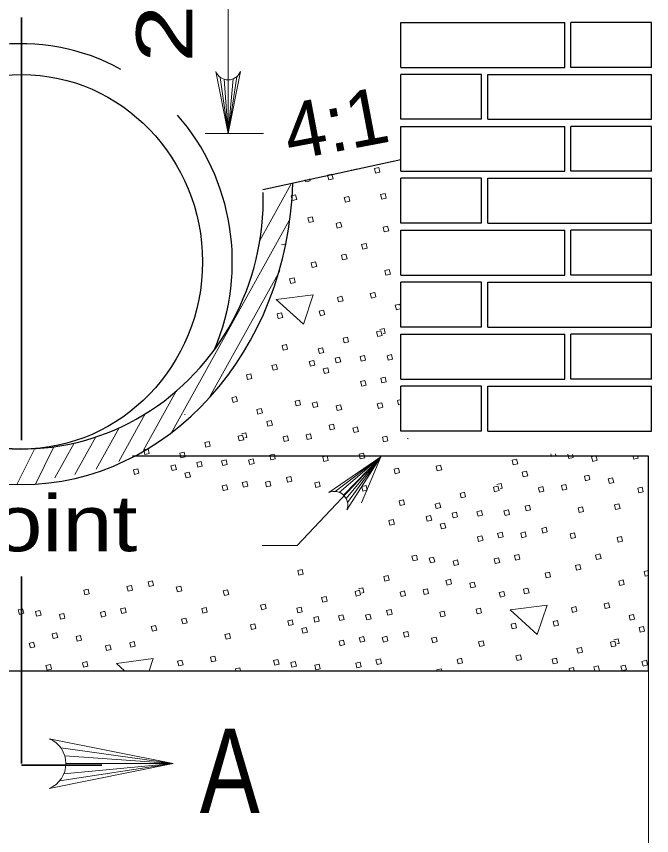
# Model space of a CAD drawing. Extents: x 750.7 to 784.7, y 860.1 to 882.1.
# Drawn here: x 763.779 to 765.592, y 862.482 to 864.82 of the extents above; entities that cross this region are included whole.
import ezdxf
from ezdxf.enums import TextEntityAlignment as Align

# ---------------------------------------------------------------- set-up
doc = ezdxf.new("R2010")
doc.units = 0
doc.header["$LTSCALE"] = 0.064
doc.layers.add('1', color=7, linetype='Continuous', lineweight=13)

msp = doc.modelspace()

# ---------------------------------------------------------------- linework, layer by layer
at = {"layer": '1'}
for p, q in [((764.38325, 864.48525), (764.38325, 864.95308)), ((764.36083, 864.64558), (764.38325, 864.48525)), ((764.40808, 864.6475), (764.38325, 864.48525)), ((764.37192, 864.64017), (764.38325, 864.48525)), ((764.39767, 864.64133), (764.38325, 864.48525)), ((764.38325, 864.6385), (764.38325, 864.48525)), ((764.48417, 864.48525), (764.31717, 864.48525)), ((764.47383, 864.18017), (764.56233, 864.3395)), ((764.21975, 863.62858), (764.55783, 864.23733)), ((764.53542, 864.16725), (764.54525, 864.16958)), ((764.33, 863.733), (764.53033, 864.09367)), ((764.8165, 863.92617), (764.82858, 863.929)), ((764.1415, 863.58175), (764.23475, 863.74975)), ((764.07142, 863.54967), (764.14667, 863.68525)), ((764.25867, 863.68333), (764.26083, 863.68383)), ((764.00667, 863.52733), (764.07233, 863.6455)), ((763.94592, 863.51208), (764.00533, 863.61917)), ((764.42142, 863.62842), (764.4335, 863.63133)), ((763.88825, 863.50242), (763.94342, 863.60167)), ((763.78042, 863.48383), (763.82992, 863.58292)), ((763.83325, 863.48492), (763.88517, 863.58883)), ((764.8195, 863.56292), (764.57992, 863.30967)), ((764.68883, 863.46375), (764.8195, 863.56292)), ((764.7005, 863.46092), (764.8195, 863.56292)), ((764.71283, 863.45292), (764.8195, 863.56292)), ((764.71983, 863.44392), (764.8195, 863.56292)), ((764.724, 863.43225), (764.8195, 863.56292)), ((764.8195, 863.56292), (764.76358, 863.43117)), ((765.15017, 863.48325), (765.16233, 863.48617)), ((764.4805, 863.30967), (764.57992, 863.30967)), ((765.58317, 863.23833), (765.58325, 863.23808)), ((764.75517, 863.18558), (764.76725, 863.18842)), ((765.58325, 863.15042), (765.58325, 862.085)), ((765.48392, 863.04033), (765.49608, 863.04325)), ((764.15792, 862.95208), (764.16958, 862.987)), ((765.36875, 862.9615), (765.371, 862.95208)), ((764.41642, 862.96033), (764.41842, 862.95208)), ((764.99175, 862.95733), (764.993, 862.95208)), ((763.90592, 862.73183), (764.2265, 862.687)), ((763.91675, 862.70967), (764.2265, 862.687)), ((763.90217, 862.63742), (764.2265, 862.687)), ((763.91442, 862.65817), (764.2265, 862.687)), ((763.92008, 862.687), (764.2265, 862.687))]:
    msp.add_line(p, q, dxfattribs=at)
at = {"layer": '1', "lineweight": 35}
for p, q in [((763.79367, 863.61058), (763.79367, 864.81675)), ((763.79367, 862.687), (763.79367, 863.22092)), ((764.02267, 862.68275), (763.79367, 862.68275))]:
    msp.add_line(p, q, dxfattribs=at)
at = {"layer": '1', "lineweight": 25}
for p, q in [((765.36175, 864.67417), (765.36175, 864.80217)), ((765.59183, 864.67417), (765.36175, 864.67417)), ((764.8765, 864.52583), (764.8765, 864.65392)), ((765.10658, 864.52583), (764.8765, 864.52583)), ((765.36175, 864.37758), (765.36175, 864.50567)), ((764.482, 864.32533), (764.8765, 864.41117)), ((765.59183, 864.37758), (765.36175, 864.37758)), ((764.8765, 864.22933), (764.8765, 864.35742)), ((765.10658, 864.22933), (764.8765, 864.22933)), ((765.36175, 864.08108), (765.36175, 864.20908)), ((764.8765, 863.93283), (764.8765, 864.06083)), ((765.59183, 864.08108), (765.36175, 864.08108)), ((765.10658, 863.93283), (764.8765, 863.93283)), ((765.36175, 863.7845), (765.36175, 863.91258)), ((765.59183, 863.7845), (765.36175, 863.7845)), ((764.8765, 863.63625), (764.8765, 863.76433)), ((765.10658, 863.63625), (764.8765, 863.63625)), ((765.58325, 863.56433), (764.10992, 863.56433)), ((765.58325, 862.95208), (765.58325, 863.56433)), ((760.59067, 862.95208), (765.58325, 862.95208))]:
    msp.add_line(p, q, dxfattribs=at)
for points in [[(764.8765, 864.67417), (764.8765, 864.80217), (765.34417, 864.80217)], [(764.8765, 864.67417), (765.34417, 864.67417), (765.34417, 864.80217)], [(765.59183, 864.67417), (765.59183, 864.80217), (765.36175, 864.80217)], [(765.10658, 864.52583), (765.10658, 864.65392), (764.8765, 864.65392)], [(765.12425, 864.52583), (765.12425, 864.65392), (765.59192, 864.65392)], [(765.12425, 864.52583), (765.59192, 864.52583), (765.59192, 864.65392)], [(764.8765, 864.37758), (764.8765, 864.50567), (765.34417, 864.50567)], [(764.8765, 864.37758), (765.34417, 864.37758), (765.34417, 864.50567)], [(765.59183, 864.37758), (765.59183, 864.50567), (765.36175, 864.50567)], [(765.10658, 864.22933), (765.10658, 864.35742), (764.8765, 864.35742)], [(765.12425, 864.22933), (765.12425, 864.35742), (765.59192, 864.35742)], [(765.12425, 864.22933), (765.59192, 864.22933), (765.59192, 864.35742)], [(764.8765, 864.08108), (764.8765, 864.20908), (765.34417, 864.20908)], [(764.8765, 864.08108), (765.34417, 864.08108), (765.34417, 864.20908)], [(765.59183, 864.08108), (765.59183, 864.20908), (765.36175, 864.20908)], [(765.10658, 863.93283), (765.10658, 864.06083), (764.8765, 864.06083)], [(765.12425, 863.93283), (765.12425, 864.06083), (765.59192, 864.06083)], [(765.12425, 863.93283), (765.59192, 863.93283), (765.59192, 864.06083)], [(764.8765, 863.7845), (764.8765, 863.91258), (765.34417, 863.91258)], [(764.8765, 863.7845), (765.34417, 863.7845), (765.34417, 863.91258)], [(765.59183, 863.7845), (765.59183, 863.91258), (765.36175, 863.91258)], [(765.10658, 863.63625), (765.10658, 863.76433), (764.8765, 863.76433)], [(765.12425, 863.63625), (765.12425, 863.76433), (765.59192, 863.76433)], [(765.12425, 863.63625), (765.59192, 863.63625), (765.59192, 863.76433)]]:
    msp.add_lwpolyline(points, dxfattribs=at)
at = {"layer": '1'}
for points in [[(764.41867, 864.66233), (764.38325, 864.48525), (764.34783, 864.66233)], [(764.74808, 864.384), (764.74825, 864.38325), (764.73575, 864.38025), (764.7355, 864.38133)], [(764.61583, 864.356), (764.61725, 864.35), (764.60467, 864.347), (764.60317, 864.35333)], [(764.82858, 863.929), (764.83175, 863.91575), (764.82542, 863.91425)], [(764.8765, 863.71208), (764.86967, 863.7105), (764.86642, 863.72375), (764.8765, 863.72608)], [(764.4335, 863.63133), (764.43675, 863.61808), (764.43042, 863.6165)], [(764.89658, 863.6145), (764.89567, 863.61433), (764.89533, 863.61583)], [(765.31758, 863.57092), (765.31875, 863.56608), (765.30617, 863.56308), (765.30425, 863.57125)], [(765.36592, 863.56967), (765.36808, 863.56075), (765.3555, 863.55775), (765.35258, 863.57)], [(764.67083, 863.46042), (764.8195, 863.56292), (764.72158, 863.41117)], [(765.55192, 863.56517), (765.5535, 863.55867), (765.54092, 863.55567), (765.53858, 863.5655)], [(765.16233, 863.48617), (765.1655, 863.47292), (765.15917, 863.47133)], [(765.58325, 863.42317), (765.58308, 863.42317), (765.58325, 863.423)], [(765.58325, 863.22433), (765.57383, 863.22208), (765.57058, 863.23533), (765.58317, 863.23833)], [(764.76725, 863.18842), (764.7705, 863.17517), (764.76408, 863.17367)], [(765.49608, 863.04325), (765.49925, 863.03), (765.49292, 863.02842)], [(764.16958, 862.987), (764.06417, 862.97292), (764.08733, 862.95208)], [(765.35775, 862.95208), (765.35617, 862.9585), (765.36875, 862.9615)], [(765.42983, 862.95208), (765.42717, 862.96317), (765.43975, 862.96617)], [(765.43975, 862.96617), (765.44292, 862.95292), (765.4395, 862.95208)], [(764.40517, 862.95208), (764.40392, 862.95733), (764.41642, 862.96033)], [(764.97967, 862.95208), (764.97917, 862.95433), (764.99175, 862.95733)], [(763.87242, 862.61617), (764.2265, 862.687), (763.87242, 862.75783)]]:
    msp.add_lwpolyline(points, dxfattribs=at)
for points in [[(764.81325, 864.38842), (764.81642, 864.37517), (764.80383, 864.37217), (764.80067, 864.38542)], [(764.67958, 864.36917), (764.68275, 864.35592), (764.67025, 864.353), (764.667, 864.36617)], [(764.57575, 864.3105), (764.579, 864.29725), (764.56642, 864.29425), (764.56317, 864.3075)], [(764.72725, 864.30592), (764.73042, 864.29267), (764.71792, 864.28967), (764.71467, 864.30292)], [(764.83108, 864.314), (764.83425, 864.30083), (764.82175, 864.29783), (764.8185, 864.31108)], [(764.62342, 864.24717), (764.62667, 864.23392), (764.61408, 864.231), (764.61092, 864.24425)], [(764.70425, 864.23183), (764.70742, 864.21858), (764.69483, 864.21558), (764.69167, 864.22883)], [(764.83825, 864.22108), (764.8415, 864.20783), (764.82892, 864.20483), (764.82567, 864.21808)], [(764.77683, 864.17108), (764.78, 864.15783), (764.76742, 864.15483), (764.76425, 864.16808)], [(764.71933, 864.14075), (764.7225, 864.12758), (764.70992, 864.12458), (764.70675, 864.13783)], [(764.63275, 864.11942), (764.63592, 864.10617), (764.62342, 864.10317), (764.62017, 864.11642)], [(764.84308, 864.097), (764.84625, 864.08375), (764.83375, 864.08075), (764.8305, 864.094)], [(764.57133, 864.07342), (764.5745, 864.06017), (764.56192, 864.05717), (764.55875, 864.07042)], [(764.626, 864.02525), (764.5205, 864.01125), (764.59808, 863.94158)], [(764.70792, 864.02075), (764.71108, 864.0075), (764.69858, 864.0045), (764.69533, 864.01775)], [(764.80158, 864.032), (764.80475, 864.01875), (764.79225, 864.01575), (764.789, 864.029)], [(764.87283, 863.99867), (764.876, 863.98542), (764.8635, 863.98242), (764.86025, 863.99567)], [(764.53567, 863.9735), (764.53892, 863.96025), (764.52633, 863.95733), (764.52317, 863.9705)], [(764.65583, 863.98158), (764.65908, 863.96833), (764.6465, 863.96533), (764.64333, 863.97858)], [(764.8195, 863.92217), (764.82267, 863.90892), (764.81008, 863.90592), (764.80692, 863.91917)], [(764.724, 863.90425), (764.72717, 863.891), (764.71458, 863.888), (764.71142, 863.90125)], [(764.54983, 863.88308), (764.553, 863.86983), (764.54042, 863.86683), (764.53725, 863.88008)], [(764.65283, 863.87383), (764.65608, 863.86058), (764.6435, 863.85758), (764.64033, 863.87083)], [(764.77225, 863.85192), (764.77542, 863.83867), (764.76292, 863.83567), (764.75967, 863.84892)], [(764.84942, 863.85425), (764.85258, 863.841), (764.84, 863.838), (764.83683, 863.85125)], [(764.52058, 863.82642), (764.52383, 863.81317), (764.51125, 863.81017), (764.50808, 863.82342)], [(764.62742, 863.83775), (764.63058, 863.8245), (764.618, 863.8215), (764.61483, 863.83475)], [(764.70125, 863.84725), (764.7045, 863.834), (764.69192, 863.831), (764.68867, 863.84425)], [(764.66742, 863.81642), (764.67058, 863.80317), (764.65808, 863.80017), (764.65483, 863.81342)], [(764.448, 863.79925), (764.45125, 863.786), (764.43867, 863.783), (764.43542, 863.79625)], [(764.77383, 863.78033), (764.777, 863.76708), (764.76442, 863.76408), (764.76125, 863.77733)], [(764.83133, 863.79), (764.8345, 863.77675), (764.82192, 863.77375), (764.81875, 863.787)], [(764.4065, 863.73433), (764.40975, 863.72108), (764.39717, 863.71808), (764.394, 863.73133)], [(764.58675, 863.72458), (764.58992, 863.71133), (764.57742, 863.70833), (764.57417, 863.72158)], [(764.63608, 863.71917), (764.63925, 863.70592), (764.62675, 863.70292), (764.6235, 863.71617)], [(764.70425, 863.71108), (764.70742, 863.69792), (764.69483, 863.69492), (764.69167, 863.70817)], [(764.8215, 863.71708), (764.82467, 863.70383), (764.81208, 863.70083), (764.80892, 863.71408)], [(764.47775, 863.70092), (764.481, 863.68775), (764.46842, 863.68475), (764.46517, 863.698)], [(764.50625, 863.66658), (764.50942, 863.65333), (764.49692, 863.65033), (764.49367, 863.66358)], [(764.68375, 863.65583), (764.687, 863.64267), (764.67442, 863.63967), (764.67125, 863.65292)], [(764.75192, 863.64783), (764.75508, 863.63458), (764.7425, 863.63158), (764.73933, 863.64483)], [(764.42442, 863.62442), (764.42758, 863.61117), (764.41508, 863.60817), (764.41183, 863.62142)], [(764.55275, 863.62267), (764.55592, 863.60942), (764.54333, 863.60642), (764.54017, 863.61967)], [(764.61825, 863.62858), (764.62142, 863.61533), (764.60892, 863.61233), (764.60567, 863.62558)], [(764.83592, 863.6215), (764.83908, 863.60825), (764.82658, 863.60525), (764.82333, 863.6185)], [(764.32892, 863.6065), (764.33208, 863.59325), (764.3195, 863.59025), (764.31633, 863.6035)], [(764.15475, 863.58533), (764.15792, 863.57208), (764.14542, 863.56917), (764.14217, 863.58233)], [(764.25783, 863.57608), (764.261, 863.56283), (764.24842, 863.55992), (764.24525, 863.57308)], [(764.51442, 863.56992), (764.51767, 863.55667), (764.50508, 863.55367), (764.50192, 863.56692)], [(764.76975, 863.57342), (764.773, 863.56017), (764.76042, 863.55725), (764.75725, 863.57042)], [(764.30617, 863.54958), (764.30942, 863.53633), (764.29683, 863.53333), (764.29367, 863.54658)], [(764.37717, 863.55425), (764.38042, 863.541), (764.36783, 863.538), (764.36458, 863.55125)], [(764.45433, 863.5565), (764.4575, 863.54325), (764.44492, 863.54025), (764.44175, 863.5535)], [(764.66592, 863.56533), (764.66917, 863.55208), (764.65658, 863.54908), (764.65342, 863.56233)], [(765.20658, 863.55575), (765.20975, 863.5425), (765.19717, 863.5395), (765.194, 863.55275)], [(765.433, 863.56592), (765.43625, 863.55267), (765.42367, 863.54967), (765.42042, 863.56292)], [(764.12558, 863.52875), (764.12875, 863.5155), (764.11617, 863.5125), (764.113, 863.52575)], [(764.23233, 863.54), (764.2355, 863.52675), (764.223, 863.52375), (764.21975, 863.537)], [(764.86942, 863.53067), (764.87258, 863.51742), (764.86008, 863.51442), (764.85683, 863.52767)], [(764.98958, 863.53867), (764.99283, 863.52542), (764.98025, 863.52242), (764.97708, 863.53567)], [(764.27233, 863.51875), (764.27558, 863.5055), (764.263, 863.5025), (764.25983, 863.51575)], [(764.56217, 863.50658), (764.56533, 863.49333), (764.55275, 863.49033), (764.54958, 863.50358)], [(765.23508, 863.52142), (765.23825, 863.50817), (765.22567, 863.50517), (765.2225, 863.51842)], [(765.41258, 863.51067), (765.41575, 863.49742), (765.40325, 863.49442), (765.4, 863.50767)], [(765.48067, 863.50267), (765.48392, 863.48942), (765.47133, 863.48642), (765.46817, 863.49967)], [(764.37875, 863.48267), (764.38192, 863.46942), (764.36933, 863.46642), (764.36617, 863.47967)], [(764.43625, 863.49233), (764.43942, 863.47908), (764.42692, 863.47608), (764.42367, 863.48933)], [(764.502, 863.49325), (764.50517, 863.48), (764.49267, 863.477), (764.48942, 863.49025)], [(764.64292, 863.49125), (764.64608, 863.478), (764.63358, 863.475), (764.63033, 863.48825)], [(764.77692, 863.48042), (764.78017, 863.46725), (764.76758, 863.46425), (764.76442, 863.4775)], [(765.15325, 863.47925), (765.15642, 863.466), (765.14383, 863.463), (765.14067, 863.47625)], [(765.2815, 863.4775), (765.28475, 863.46425), (765.27217, 863.46125), (765.269, 863.4745)], [(765.34708, 863.48342), (765.35025, 863.47017), (765.33767, 863.46717), (765.3345, 863.48042)], [(765.56467, 863.47633), (765.56792, 863.46308), (765.55533, 863.46008), (765.55217, 863.47333)], [(765.05767, 863.46133), (765.06092, 863.44808), (765.04833, 863.44508), (765.04517, 863.45833)], [(764.88358, 863.44017), (764.88675, 863.42692), (764.87417, 863.42392), (764.871, 863.43717)], [(764.98658, 863.43092), (764.98983, 863.41767), (764.97725, 863.41467), (764.97408, 863.42792)], [(765.49858, 863.42825), (765.50175, 863.415), (765.48925, 863.412), (765.486, 863.42525)], [(765.106, 863.409), (765.10917, 863.39575), (765.09658, 863.39275), (765.09342, 863.406)], [(765.18308, 863.41133), (765.18633, 863.39808), (765.17375, 863.39508), (765.17058, 863.40833)], [(765.24325, 863.42475), (765.24642, 863.4115), (765.23392, 863.4085), (765.23067, 863.42175)], [(765.39475, 863.42017), (765.39792, 863.40692), (765.38542, 863.40392), (765.38217, 863.41717)], [(764.85433, 863.3835), (764.85758, 863.37033), (764.845, 863.36733), (764.84183, 863.38058)], [(764.96117, 863.39483), (764.96433, 863.38158), (764.95175, 863.37858), (764.94858, 863.39183)], [(765.035, 863.40433), (765.03817, 863.39117), (765.02567, 863.38817), (765.02242, 863.40142)], [(765.00117, 863.37358), (765.00433, 863.36033), (764.99183, 863.35733), (764.98858, 863.37058)], [(765.29092, 863.36142), (765.29417, 863.34817), (765.28158, 863.34517), (765.27842, 863.35842)], [(765.1075, 863.3375), (765.11075, 863.32425), (765.09817, 863.32125), (765.095, 863.3345)], [(765.16508, 863.34708), (765.16825, 863.33383), (765.15567, 863.33092), (765.1525, 863.34408)], [(765.23083, 863.34808), (765.234, 863.33483), (765.22142, 863.33183), (765.21825, 863.34508)], [(765.37175, 863.346), (765.37492, 863.33275), (765.36233, 863.32975), (765.35917, 863.343)], [(765.50575, 863.33525), (765.50892, 863.322), (765.49642, 863.319), (765.49317, 863.33225)], [(764.9205, 863.28167), (764.92367, 863.26842), (764.91108, 863.26542), (764.90792, 863.27867)], [(764.96983, 863.27625), (764.973, 863.263), (764.9605, 863.26), (764.95725, 863.27325)], [(765.03792, 863.26825), (765.04117, 863.255), (765.02858, 863.252), (765.02542, 863.26525)], [(765.15525, 863.27417), (765.15842, 863.26092), (765.14583, 863.25792), (765.14267, 863.27117)], [(765.21275, 863.28383), (765.21592, 863.27058), (765.20342, 863.26758), (765.20017, 863.28083)], [(765.44425, 863.28533), (765.4475, 863.27208), (765.43492, 863.26908), (765.43175, 863.28233)], [(764.59458, 863.241), (764.59775, 863.22775), (764.58517, 863.22475), (764.582, 863.238)], [(765.38675, 863.255), (765.39, 863.24175), (765.37742, 863.23875), (765.37425, 863.252)], [(764.84, 863.22375), (764.84317, 863.2105), (764.83067, 863.2075), (764.82742, 863.22075)], [(765.30025, 863.23367), (765.30342, 863.22042), (765.29092, 863.21742), (765.28767, 863.23067)], [(764.10692, 863.1955), (764.11017, 863.18225), (764.09758, 863.17925), (764.09442, 863.1925)], [(764.16708, 863.20892), (764.17025, 863.19567), (764.15775, 863.19267), (764.1545, 863.20592)], [(765.0175, 863.213), (765.02075, 863.19975), (765.00817, 863.19675), (765.00492, 863.21)], [(765.08567, 863.20492), (765.08883, 863.19167), (765.07625, 863.18875), (765.07308, 863.20192)], [(765.51058, 863.21117), (765.51375, 863.19792), (765.50117, 863.19492), (765.498, 863.20817)], [(763.98367, 863.18492), (763.98683, 863.17175), (763.97433, 863.16875), (763.97108, 863.182)], [(764.24783, 863.1935), (764.25108, 863.18025), (764.2385, 863.17725), (764.23525, 863.1905)], [(764.38183, 863.18275), (764.38508, 863.1695), (764.3725, 863.1665), (764.36933, 863.17975)], [(764.75817, 863.18158), (764.76133, 863.16833), (764.74875, 863.16533), (764.74558, 863.17858)], [(764.8865, 863.17975), (764.88967, 863.1665), (764.87708, 863.1635), (764.87392, 863.17675)], [(764.952, 863.18575), (764.95517, 863.1725), (764.94258, 863.1695), (764.93942, 863.18275)], [(765.16967, 863.17858), (765.17283, 863.16542), (765.16025, 863.16242), (765.15708, 863.17567)], [(765.23883, 863.18767), (765.242, 863.17442), (765.22942, 863.17142), (765.22625, 863.18467)], [(764.66267, 863.16367), (764.66583, 863.15042), (764.65325, 863.14742), (764.65008, 863.16067)], [(763.79658, 863.12917), (763.79983, 863.11592), (763.78725, 863.11292), (763.78408, 863.12617)], [(764.08892, 863.13133), (764.09208, 863.11808), (764.0795, 863.11508), (764.07633, 863.12833)], [(764.32042, 863.13275), (764.32358, 863.11958), (764.31108, 863.11658), (764.30783, 863.12983)], [(764.4885, 863.1425), (764.49167, 863.12925), (764.47917, 863.12625), (764.47592, 863.1395)], [(764.59158, 863.13325), (764.59475, 863.12), (764.58217, 863.117), (764.579, 863.13025)], [(764.84817, 863.127), (764.85142, 863.11375), (764.83883, 863.11075), (764.83558, 863.124)], [(765.1035, 863.13058), (765.10667, 863.11733), (765.09417, 863.11433), (765.09092, 863.12758)], [(765.29342, 863.1395), (765.188, 863.1255), (765.26558, 863.05575)], [(765.37542, 863.135), (765.37858, 863.12175), (765.366, 863.11875), (765.36283, 863.132)], [(765.46908, 863.14625), (765.47225, 863.133), (765.45967, 863.13), (765.4565, 863.14325)], [(763.846, 863.12375), (763.84917, 863.1105), (763.83658, 863.1075), (763.83342, 863.12075)], [(763.91408, 863.11575), (763.91725, 863.1025), (763.90475, 863.0995), (763.9015, 863.11275)], [(764.03133, 863.12167), (764.03458, 863.10842), (764.022, 863.10542), (764.01883, 863.11867)], [(764.26292, 863.1025), (764.26608, 863.08925), (764.25358, 863.08625), (764.25033, 863.0995)], [(764.63992, 863.10667), (764.64317, 863.09342), (764.63058, 863.09042), (764.62742, 863.10367)], [(764.71092, 863.11133), (764.71408, 863.09808), (764.70158, 863.09508), (764.69833, 863.10833)], [(764.78808, 863.11367), (764.79125, 863.10042), (764.77867, 863.09742), (764.7755, 863.11067)], [(764.99967, 863.12242), (765.00283, 863.10917), (764.99033, 863.10617), (764.98708, 863.11942)], [(765.54033, 863.11292), (765.5435, 863.09967), (765.53092, 863.09667), (765.52775, 863.10992)], [(764.17633, 863.08108), (764.17958, 863.06783), (764.167, 863.06483), (764.16383, 863.07808)], [(764.45933, 863.08583), (764.4625, 863.07258), (764.44992, 863.06958), (764.44675, 863.08283)], [(764.56608, 863.09708), (764.56925, 863.08392), (764.55667, 863.08092), (764.5535, 863.09417)], [(765.20317, 863.08775), (765.20633, 863.0745), (765.19383, 863.0715), (765.19058, 863.08475)], [(765.32333, 863.09575), (765.32658, 863.08258), (765.314, 863.07958), (765.31075, 863.09283)], [(765.56883, 863.0785), (765.572, 863.06525), (765.55942, 863.06233), (765.55625, 863.0755)], [(763.89367, 863.0605), (763.89683, 863.04725), (763.88425, 863.04425), (763.88108, 863.0575)], [(764.38667, 863.05867), (764.38992, 863.04542), (764.37733, 863.04242), (764.37417, 863.05567)], [(764.60608, 863.07583), (764.60933, 863.06258), (764.59675, 863.05958), (764.5935, 863.07283)], [(764.89583, 863.06375), (764.89908, 863.0505), (764.8865, 863.0475), (764.88333, 863.06075)], [(763.82808, 863.03317), (763.83133, 863.02), (763.81875, 863.017), (763.81558, 863.03025)], [(763.96175, 863.05242), (763.965, 863.03917), (763.95242, 863.03617), (763.94925, 863.04942)], [(764.11492, 863.03517), (764.11817, 863.02192), (764.10558, 863.01892), (764.10233, 863.03217)], [(764.7125, 863.03975), (764.71567, 863.0265), (764.70308, 863.0235), (764.69992, 863.03675)], [(764.77, 863.04942), (764.77317, 863.03617), (764.76067, 863.03317), (764.75742, 863.04642)], [(764.83575, 863.05033), (764.83892, 863.03708), (764.82642, 863.03408), (764.82317, 863.04733)], [(764.97667, 863.04833), (764.97983, 863.03508), (764.96725, 863.03208), (764.96408, 863.04533)], [(765.11067, 863.03758), (765.11392, 863.02433), (765.10133, 863.02133), (765.09808, 863.03458)], [(765.48692, 863.03633), (765.49017, 863.02317), (765.47758, 863.02017), (765.47442, 863.03342)], [(764.04575, 863.02608), (764.049, 863.01283), (764.03642, 863.00983), (764.03325, 863.02308)], [(765.39142, 863.01842), (765.39467, 863.00517), (765.38208, 863.00225), (765.37892, 863.01542)], [(764.34517, 862.99367), (764.34842, 862.9805), (764.33583, 862.9775), (764.33267, 862.99075)], [(764.52542, 862.98392), (764.52858, 862.97075), (764.51608, 862.96775), (764.51283, 862.981)], [(764.81767, 862.98608), (764.82092, 862.97292), (764.80833, 862.96992), (764.80508, 862.98317)], [(765.04925, 862.98758), (765.05242, 862.97433), (765.03983, 862.97133), (765.03667, 862.98458)], [(765.21725, 862.99733), (765.2205, 862.98408), (765.20792, 862.98108), (765.20475, 862.99433)], [(765.32033, 862.988), (765.32358, 862.97483), (765.311, 862.97183), (765.30783, 862.98508)], [(763.87583, 862.96992), (763.879, 862.95667), (763.86642, 862.95367), (763.86325, 862.96692)], [(763.97967, 862.97808), (763.98283, 862.96483), (763.97025, 862.96183), (763.96708, 862.97508)], [(764.2515, 862.9825), (764.25475, 862.96925), (764.24217, 862.96625), (764.239, 862.9795)], [(764.57475, 862.97858), (764.57792, 862.96533), (764.56542, 862.96233), (764.56217, 862.97558)], [(764.64292, 862.9705), (764.64608, 862.95733), (764.6335, 862.95433), (764.63033, 862.9675)], [(764.76017, 862.9765), (764.76333, 862.96325), (764.75083, 862.96025), (764.74758, 862.9735)], [(765.51683, 862.96842), (765.52008, 862.95517), (765.5075, 862.95217), (765.50433, 862.96542)], [(765.577, 862.98183), (765.58017, 862.96858), (765.56758, 862.96558), (765.56442, 862.97883)]]:
    msp.add_lwpolyline(points, close=True, dxfattribs=at)
for centre, radius, start, end in [((764.38322, 864.67666), 0.03822, 202.08782, 337.91395), ((764.68629, 863.42553), 0.03822, 337.96235, 113.78848), ((763.84379, 862.68705), 0.07644, 292.08605, 67.91218)]:
    msp.add_arc(centre, radius, start, end, dxfattribs=at)
at = {"layer": '1', "lineweight": 25}
for centre, major_axis, ratio, start_param, end_param in [((763.79367, 864.11909), (0, -0.62258), 0.966184, 2.6512367, 5.125903), ((763.79367, 864.11909), (0, -0.62258), 0.966184, 1.1572883, 2.3088261), ((763.79367, 864.37492), (0, -0.89117), 0.869565, 4.747022, 7.8193474), ((763.79367, 864.29853), (0, 0.71385), 0.966184, 1.5331043, 4.7385268)]:
    msp.add_ellipse(centre, major_axis=major_axis, ratio=ratio, start_param=start_param, end_param=end_param, dxfattribs=at)
msp.add_ellipse((763.79367, 864.11909), major_axis=(0, 0.53442), ratio=0.966184, dxfattribs=at)

# ---------------------------------------------------------------- texts
at = {"layer": '1', "width": 1.4}
msp.add_text('24" [600]', height=0.16, rotation=90, dxfattribs=at).set_placement((764.281, 865.28138), align=Align.CENTER)
at = {"layer": '1'}
msp.add_text('4:1', height=0.16, rotation=10.71, dxfattribs=at).set_placement((764.55883, 864.40808))
for s, height, width, p in [('Constr. joint', 0.16, 1.2, (762.7545, 863.293)), ('A', 0.24, 0.8, (764.30225, 862.54633))]:
    msp.add_text(s, height=height, dxfattribs=dict(at, width=width)).set_placement(p)

doc.saveas('drawing.dxf')
